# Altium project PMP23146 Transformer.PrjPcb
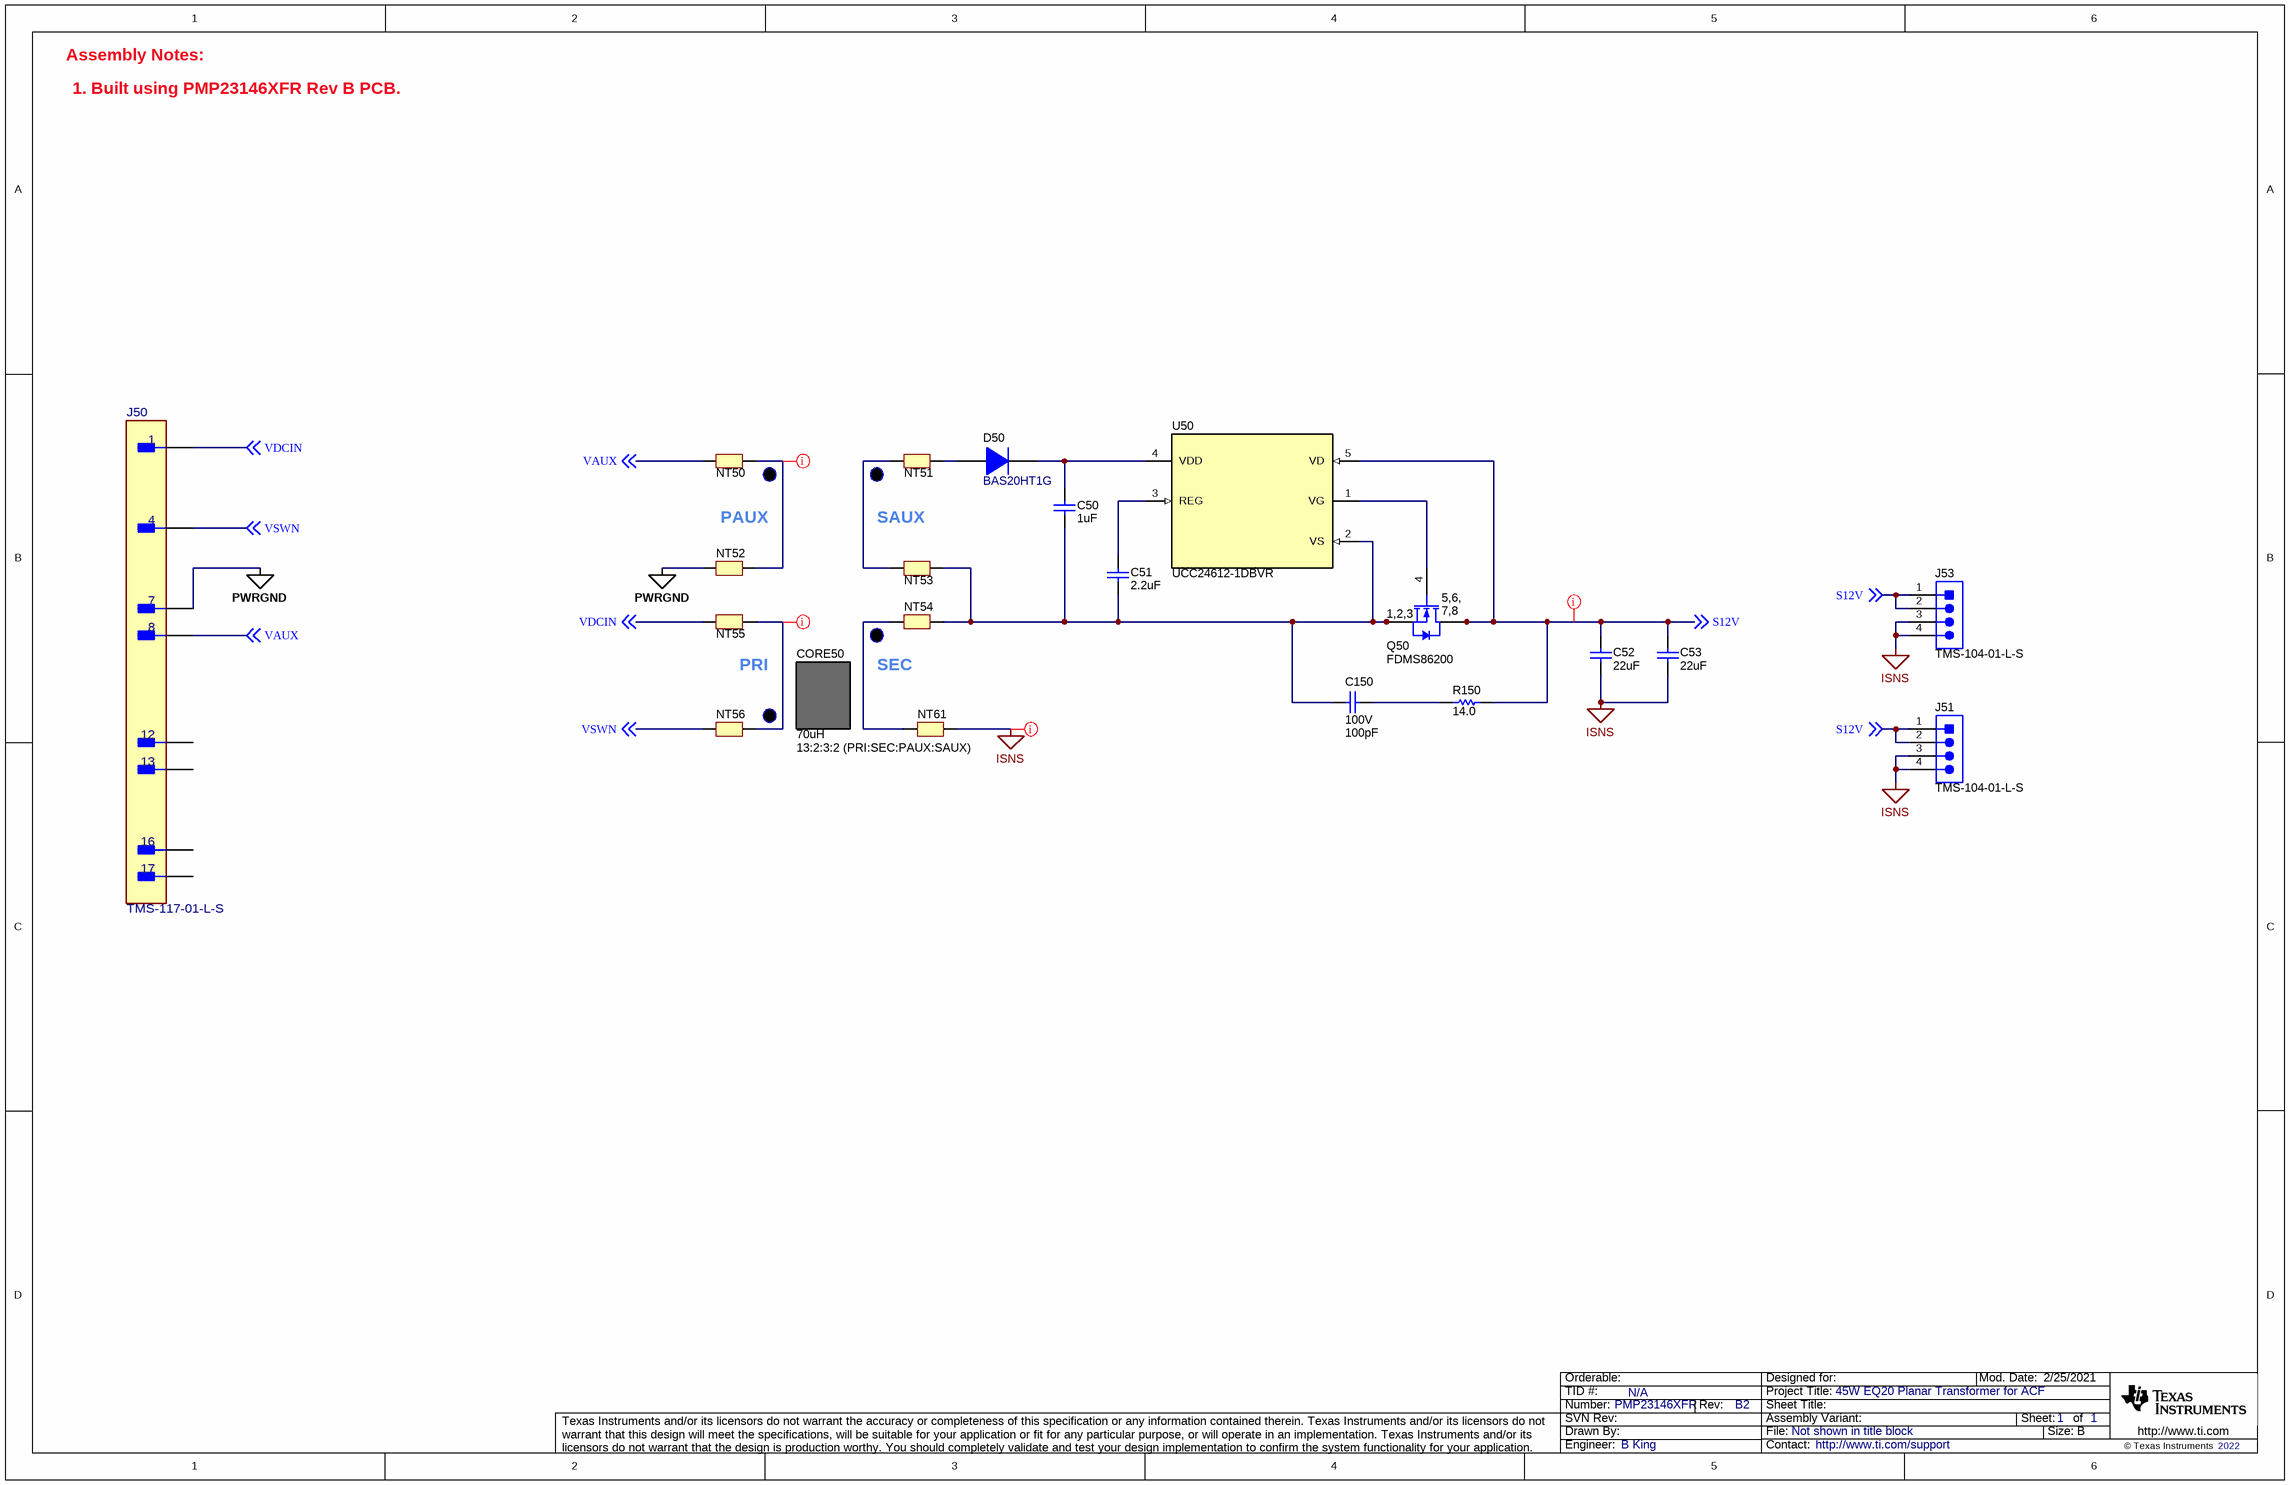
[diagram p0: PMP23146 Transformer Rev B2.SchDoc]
TID: N/A; TechSupport: http://www.ti.com/support; SCH_Rev: B2; PRJ_Title: 45W EQ20 Planar Transformer for ACF; PRJ_Number: PMP23146XFR; PRJ_Engineer: B King; PCB_Rev: B2; PCB_Layout: B King; CopyrightYear: 2022
1 sheet, 21 parts. Net scope: global (net labels, ports and power ports of the same name join across sheets).
Board file: PMP23146 Transformer Rev B.PcbDoc

## Sheet PMP23146 Transformer Rev B2.SchDoc
size 431 x 279 mm; Date: Not shown in title block; ApprovedBy: Not shown in title block; CheckedBy: Not shown in title block; Author: Not shown in title block; CompanyName: Not shown in title block; Engineer: Not shown in title block; Organization: Not shown in title block; Address1: Not shown in title block; Address2: Not shown in title block; Address3: Not shown in title block; Address4: Not shown in title block; DocumentNumber: 1; Revision: Use project parameter SCH_Rev; SheetNumber: 1; SheetTotal: 1; PageSetup: Record=PageOptions¦CenterHorizontal=True¦CenterVertical=True¦PrintScale=1.00¦XCorrection=1.00¦YCorrection=1.00¦PrintKind=0¦BorderSize=5000000¦LeftOffset=0¦BottomOffset=0¦Orientation=2¦PaperLength=1000¦PaperWidth=1000¦Scale=100¦PaperSource=15¦PrintQuality=600¦MediaType=1¦DitherType=10¦PaperKind=Letter¦PrintScaleMode=1

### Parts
C50  ValueDisplayed: 1uF  [0603S]  (hidden comment: GRM188R61E105KA12D)
C51  ValueDisplayed: 2.2uF  [0603S]  (hidden comment: GRM188R61C225KAAD)
C52  ValueDisplayed: 22uF  [1206_180L]  (hidden comment: C3216X5R1V226M160AC)
C53  ValueDisplayed: 22uF  [1206_180L]  (hidden comment: C3216X5R1V226M160AC)
C150  VDC_V: 100V  ValueDisplayed: 100pF  [0603S]  (hidden comment: GRM1885C2A101JA01D)
CORE50  70uH  Turn Ratio: 13:2:3:2 (PRI:SEC:PAUX:SAUX)  [PCBComponent_1]
D50  BAS20HT1G  [SOD-323]
J50  TMS-117-01-L-S  [FP-GRPB171VWVN-RC_HDR17-MFG]
J51  TMS-104-01-L-S  [Sullins_GRPB041VWVN-RC]
J53  TMS-104-01-L-S  [Sullins_GRPB041VWVN-RC]
NT50  Net-Tie  [Net-Tie_50milWide_30milLong]  (value not drawn)  (net tie, no BOM)
NT51  Net-Tie  [Net-Tie_10milWide_30milLong]  (value not drawn)  (net tie, no BOM)
NT52  Net-Tie  [Net-Tie_50milWide_30milLong]  (value not drawn)  (net tie, no BOM)
NT53  Net-Tie  [Net-Tie_10milWide_30milLong]  (value not drawn)  (net tie, no BOM)
NT54  Net-Tie  [Net-Tie_50milWide_30milLong]  (value not drawn)  (net tie, no BOM)
NT55  Net-Tie  [Net-Tie_50milWide_30milLong]  (value not drawn)  (net tie, no BOM)
NT56  Net-Tie  [Net-Tie_50milWide_30milLong]  (value not drawn)  (net tie, no BOM)
NT61  Net-Tie  [Net-Tie_50milWide_30milLong]  (value not drawn)  (net tie, no BOM)
Q50  FDMS86200  [PowerPAK_SO-8]
R150  ValueDisplayed: 14.0  [1206L]  (hidden comment: ERJ-8ENF14R0V)
U50  UCC24612-1DBVR  [DBV0005A_N]

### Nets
ISNS: C52.1 C53.1 J51.3 J51.4 J53.3 J53.4 NT61.1
PWRGND: J50.7 NT52.2
S12V: C52.2 C53.2 J51.1 J51.2 J53.1 J53.2 Q50.5(D) Q50.6(D) Q50.7(D) Q50.8(D) Q50.9(D) R150.2 U50.5(VD) ; off-sheet S12V
VAUX: J50.8 NT50.1 ; off-sheet VAUX
VDCIN: J50.1 NT55.1 ; off-sheet VDCIN
VSWN: J50.4 NT56.2 ; off-sheet VSWN
NetC50_1: C50.1 D50.1(K) U50.4(VDD)
NetC50_2: C50.2 C51.2 C150.2 NT53.2 NT54.1 Q50.1(S) Q50.2(S) Q50.3(S) U50.2(VS)
NetC51_1: C51.1 U50.3(REG)
NetC150_1: C150.1 R150.1
NetD50_2: D50.2(A) NT51.1
NetNT50_2: NT50.2 NT52.1
NetNT51_2: NT51.2 NT53.1
NetNT54_2: NT54.2 NT61.2
NetNT55_2: NT55.2 NT56.1
NetQ50_4: Q50.4(G) U50.1(VG)

Not connected (* = marked no-connect by the designer): J50 12 13 16 17

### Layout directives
net class Primary: NetNT50_2, NetNT55_2
net class Secondary: ISNS, S12V

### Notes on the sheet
- Assembly Notes:
- 1. Built using PMP23146XFR Rev B PCB.
- PAUX
- SAUX
- PRI
- SEC

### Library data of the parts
C50 = CMP-0007343-5: CAP, CERM, 1 uF, 25 V, +/- 10%, X5R, 0603; Manufacturer: MuRata; TaMin_C: -55°C; Polarized: N; SizeAreaWB_mm2: 4.68; Value1: Unknown; U/M: EA; Value: 1uF; TaMax_C: 85°C; SizeZ_mm: 1; SizeX_mm: 1.6; SizeY_mm: 0.8; Cap_Case: 0603; Value2: 25V; SizeArea_mm2: 1.28; CompType: Capacitor; Cap_F: 1µF; AEC Category: Q200
C51 = CMP-0007338-5: CAP, CERM, 2.2 uF, 16 V, +/- 10%, X5R, 0603; Manufacturer: MuRata; TaMin_C: -55°C; Polarized: N; SizeAreaWB_mm2: 4.68; Value1: Unknown; U/M: EA; Value: 2.2uF; TaMax_C: 85°C; SizeZ_mm: 1; SizeX_mm: 1.6; SizeY_mm: 0.8; Cap_Case: 0603; Value2: 16V; SizeArea_mm2: 1.28; CompType: Capacitor; Cap_F: 2.2µF; AEC Category: Q200
C52 C53 = CMP-0008667-2: CAP, CERM, 22 uF, 35 V, +/- 20%, X5R, 1206; Manufacturer: TDK; TaMin_C: -55°C; ESR_ohm: 2.398m; Polarized: N; SizeAreaWB_mm2: 10.92; Value1: 0.002398 ohm; U/M: EA; Value: 22uF; TaMax_C: 85°C; SizeZ_mm: 1.8; SizeX_mm: 3.2; SizeY_mm: 1.6; Cap_Case: 1206_180; Value2: 35V; SizeArea_mm2: 5.12; Cap_F: 22µF; IRMS_A: 4.68507A; AEC Category: Q200
C150 = CMP-0007237-4: CAP, CERM, 100 pF, 100 V, +/- 5%, C0G/NP0, 0603; Manufacturer: MuRata; TaMin_C: -55°C; Polarized: N; SizeAreaWB_mm2: 4.68; Value1: Unknown; U/M: EA; Value: 100pF; TaMax_C: 125°C; SizeZ_mm: 1; SizeX_mm: 1.6; SizeY_mm: 0.8; Cap_Case: 0603; SizeArea_mm2: 1.28; AEC Category: Q200
CORE50 = Component_1: EQ20 + I core set, N49 material, gapped to 70uH; Manufacturer: EPCOS; PartNumber: B66483G0000X149 + B66483K0000X149; CompType: Used in some BOM reports.  Useful for finding later.
D50 = CMP-0029150-2: Diode, Switching, 200 V, 0.2 A, AEC-Q101, SOD-323; Manufacturer: ON Semiconductor; Value2: 1.25V; Value1: 0.2A; SizeZ_mm: 1; Green_REACh: Incomplete; SizeArea_mm2: 3.645; Vr_V: 200V; SizeX_mm: 2.7; TJmax_C: 150°C; Io_A: 200mA; Value: 200V; Green_Lifecycle: Not Set; SizeAreaWB_mm2: 8.695; AEC Qualified: Y; AEC Category: Q101; SizeY_mm: 1.35
J50 = CMP-BK1: Connector Header Through Hole 17 position 0.050" (1.27mm); Manufacturer: Samtec; Part Number: GRPB171VWVN-RC; Conn Gender: Male; SizeZ_mm: 4.4mm; ContactFinish: Gold; Current_A: 1A; Row_Count: 1; Conn Orientation: Straight; AEC Qualified: No
J51 J53 = CMP-0054569-1: Header, 50mil, 4x1, Gold, TH; Manufacturer: Samtec; CNHeader: TRUE; Green_Lifecycle: Not Set; Green_REACh: Incomplete; CT: FALSE
NT50 NT52 NT55 NT56 = CMP-0078142-4: Single point connection between nets.
NT51 NT53 NT54 NT61 = CMP-0078142-1: Single point connection between nets.
Q50 = CMP-0000985-1: MOSFET, N-CH, 150 V, 35 A, PQFN08A; Alternate Manufacturer: None; Manufacturer: Fairchild Semiconductor; SizeZ_mm: 1.12; ChType: N; Value2: 4.2 nC; Value1: 0.03; VdsMax_V: 100V; SizeX_mm: 5.99; SizeY_mm: 4.9; Vgs_V: 20V; Value: 100V; Rdson45_ohm: 34m; SizeArea_mm2: 29.351; AEC Category: Q101; IdsMax_A: 26A; SizeAreaWB_mm2: 55.131; U/M: EA; QgTyp_nC: 4.2
R150 = CMP-0017368-3: RES, 14.0, 1%, 0.25 W, AEC-Q200 Grade 0, 1206; Manufacturer: Panasonic; Power_W: 250mW; TempCo: 100 ppm/C; Value_Code: 14R0; Value: 14.0; EIA_Code: E96; Res_ohm: 14; SizeX_mm: 3.2; SizeY_mm: 1.6; SizeZ_mm: 1.35; Value2: 0.25W; SizeArea_mm2: 5.12; AEC Qualified: Y; VDC_V: 200V; AEC Category: Q200; AEC Grade: 0; SizeAreaWB_mm2: 10.92
U50 = CMP-0013050-3: High-Frequency Multi-Mode Synchronous Rectifier Controller, DBV0005A (SOT-23-5); Manufacturer: Texas Instruments; Alternate PartNumber: UCC24612-1DBVT; SizeX_mm: 2.8; SizeY_mm: 2.9; CompType: IC; SizeZ_mm: 1.45; SizeArea_mm2: 8.12; SizeAreaWB_mm2: 14.82; AEC Category: Q200; AEC Qualified: N

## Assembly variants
001: not fitted FID1 FID2 FID3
